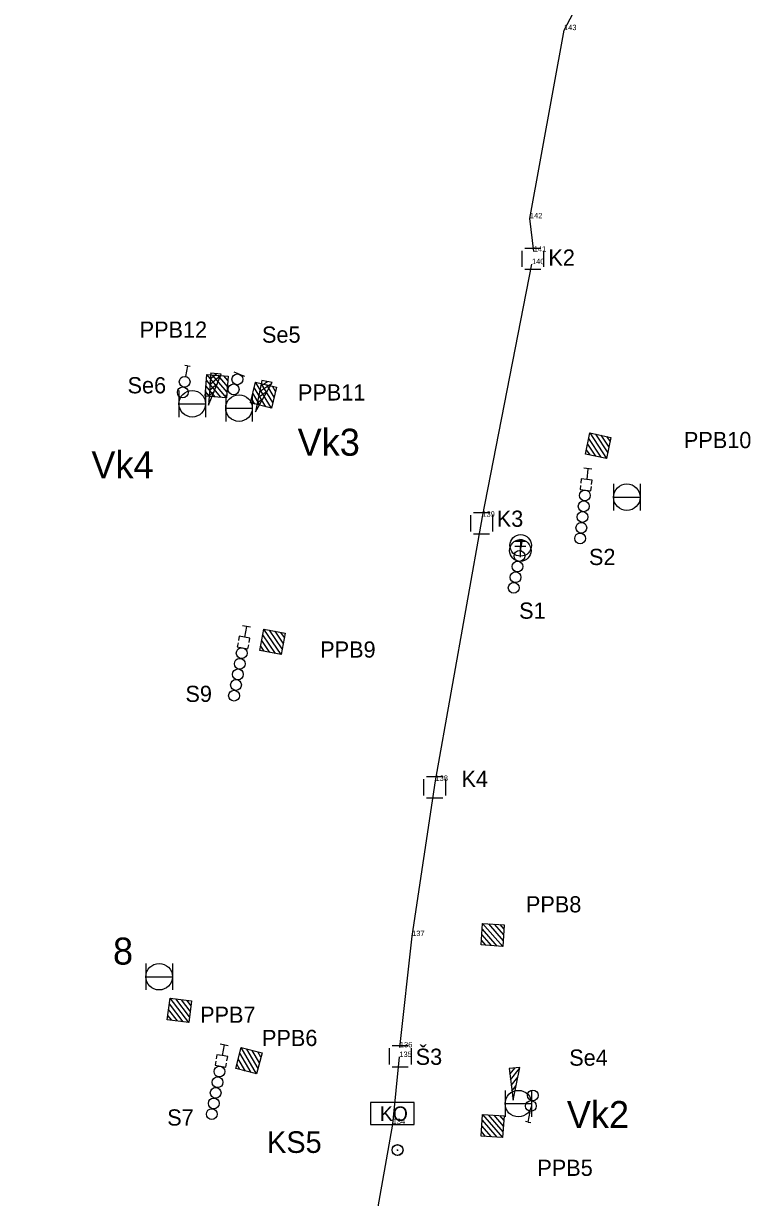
# Model space of a CAD drawing. Extents: x -866945 to -849632, y -1066564 to -1049105.
# Drawn here: x -866544.4 to -866477, y -1050152.5 to -1050043.8 of the extents above; entities that cross this region are included whole.
import ezdxf

# ---------------------------------------------------------------- set-up
doc = ezdxf.new("R2010")
doc.units = 0
for name, color, linetype in [('Vrstva 2', 7, 'Continuous'), ('Vrstva 28', 7, 'Continuous'), ('Vrstva 3', 7, 'Continuous'), ('Vrstva 31', 7, 'Continuous'), ('Vrstva 32', 7, 'Continuous'), ('Vrstva 35', 7, 'Continuous'), ('Vrstva 52', 7, 'Continuous'), ('Vrstva 6', 7, 'Continuous'), ('Vrstva 7', 7, 'Continuous')]:
    doc.layers.add(name, color=color, linetype=linetype)

msp = doc.modelspace()

# ---------------------------------------------------------------- linework, layer by layer
at = {"layer": 'Vrstva 28'}
for p, q in [((-866508.2, -1050143.71), (-866512.24, -1050143.71)), ((-866512.24, -1050143.71), (-866512.24, -1050145.73)), ((-866508.2, -1050145.73), (-866508.2, -1050143.71)), ((-866512.24, -1050145.73), (-866508.2, -1050145.73))]:
    msp.add_line(p, q, dxfattribs=at)
at = {"layer": 'Vrstva 3'}
for p, q in [((-866525.56, -1050078.48), (-866527.39, -1050076.32)), ((-866527.11, -1050077.25), (-866526.09, -1050076.38)), ((-866527.07, -1050076.73), (-866526.49, -1050076.25)), ((-866527.04, -1050076.22), (-866527.02, -1050076.21)), ((-866525.51, -1050077.95), (-866526.86, -1050076.37)), ((-866525.47, -1050077.42), (-866526.33, -1050076.41)), ((-866525.43, -1050076.89), (-866525.8, -1050076.45)), ((-866526.61, -1050078.39), (-866527.47, -1050077.38)), ((-866526.08, -1050078.43), (-866527.43, -1050076.85)), ((-866527.15, -1050077.78), (-866526.41, -1050077.15)), ((-866521.92, -1050079.31), (-866523, -1050077.53)), ((-866521.41, -1050079.44), (-866522.87, -1050077.02)), ((-866522.51, -1050077.9), (-866521.39, -1050077.16)), ((-866522.41, -1050077.39), (-866521.77, -1050076.98)), ((-866521.28, -1050078.93), (-866522.35, -1050077.15)), ((-866522.31, -1050076.88), (-866522.29, -1050076.88)), ((-866521.15, -1050078.41), (-866521.84, -1050077.28)), ((-866521.03, -1050077.9), (-866521.32, -1050077.4)), ((-866529.97, -1050077.8), (-866529.97, -1050080.26)), ((-866527.14, -1050078.35), (-866527.52, -1050077.91)), ((-866527.51, -1050077.8), (-866527.51, -1050080.26)), ((-866527.23, -1050078.82), (-866527.05, -1050078.66)), ((-866527.19, -1050078.3), (-866526.72, -1050077.9)), ((-866525.64, -1050078.2), (-866525.64, -1050080.66)), ((-866522.95, -1050079.06), (-866523.25, -1050078.56)), ((-866523.18, -1050078.2), (-866523.18, -1050080.66)), ((-866522.44, -1050079.19), (-866523.12, -1050078.05)), ((-866522.71, -1050078.93), (-866522.2, -1050078.59)), ((-866522.61, -1050078.42), (-866521.8, -1050077.88)), ((-866529.97, -1050079.03), (-866527.51, -1050079.03)), ((-866525.64, -1050079.43), (-866523.18, -1050079.43)), ((-866522.82, -1050079.45), (-866522.62, -1050079.31)), ((-866491.92, -1050081.73), (-866490.37, -1050084.1)), ((-866491.4, -1050081.84), (-866490.27, -1050083.58)), ((-866490.89, -1050081.95), (-866490.16, -1050083.06)), ((-866492.14, -1050082.77), (-866491.41, -1050083.88)), ((-866492.03, -1050082.25), (-866490.89, -1050083.99)), ((-866490.37, -1050082.06), (-866490.05, -1050082.54)), ((-866492.25, -1050083.29), (-866491.93, -1050083.77)), ((-866489.72, -1050086.45), (-866489.72, -1050088.91)), ((-866487.26, -1050086.45), (-866487.26, -1050088.91)), ((-866489.72, -1050087.68), (-866487.26, -1050087.68)), ((-866498.83, -1050091.74), (-866497.83, -1050091.74)), ((-866498.33, -1050091.74), (-866498.33, -1050092.74)), ((-866498.86, -1050092.22), (-866497.86, -1050092.22)), ((-866498.36, -1050092.22), (-866498.36, -1050093.22)), ((-866521.03, -1050102.14), (-866522.2, -1050100.42)), ((-866520.51, -1050102.23), (-866522.1, -1050099.9)), ((-866520.41, -1050101.71), (-866521.58, -1050100)), ((-866520.31, -1050101.19), (-866521.06, -1050100.09)), ((-866520.21, -1050100.67), (-866520.54, -1050100.19)), ((-866522.07, -1050101.94), (-866522.4, -1050101.46)), ((-866521.55, -1050102.04), (-866522.3, -1050100.94)), ((-866501.85, -1050127.13), (-866499.99, -1050129.26)), ((-866501.32, -1050127.16), (-866499.95, -1050128.73)), ((-866500.79, -1050127.2), (-866499.92, -1050128.2)), ((-866500.26, -1050127.23), (-866499.88, -1050127.67)), ((-866501.92, -1050128.18), (-866501.05, -1050129.18)), ((-866501.88, -1050127.65), (-866500.52, -1050129.22)), ((-866501.96, -1050128.71), (-866501.58, -1050129.15)), ((-866533.04, -1050130.83), (-866533.04, -1050133.29)), ((-866530.58, -1050130.83), (-866530.58, -1050133.29)), ((-866533.04, -1050132.06), (-866530.58, -1050132.06)), ((-866529.06, -1050136.29), (-866530.79, -1050134.06)), ((-866529, -1050135.77), (-866530.27, -1050134.12)), ((-866530.11, -1050136.16), (-866530.93, -1050135.11)), ((-866529.59, -1050136.23), (-866530.86, -1050134.58)), ((-866528.93, -1050135.24), (-866529.74, -1050134.19)), ((-866528.86, -1050134.72), (-866529.22, -1050134.26)), ((-866530.64, -1050136.09), (-866530.99, -1050135.64)), ((-866523.29, -1050140.93), (-866524.34, -1050139.14)), ((-866522.78, -1050141.06), (-866524.21, -1050138.62)), ((-866522.64, -1050140.55), (-866523.7, -1050138.76)), ((-866522.51, -1050140.03), (-866523.18, -1050138.89)), ((-866522.38, -1050139.52), (-866522.67, -1050139.02)), ((-866524.32, -1050140.66), (-866524.61, -1050140.16)), ((-866523.8, -1050140.79), (-866524.48, -1050139.65)), ((-866499.39, -1050140.58), (-866499.37, -1050140.57)), ((-866499.33, -1050141.09), (-866498.85, -1050140.51)), ((-866499.26, -1050141.61), (-866498.43, -1050140.56)), ((-866499.2, -1050142.14), (-866498.6, -1050141.37)), ((-866499.77, -1050142.58), (-866499.77, -1050145.04)), ((-866499.14, -1050142.66), (-866498.76, -1050142.17)), ((-866497.31, -1050142.58), (-866497.31, -1050145.04)), ((-866499.77, -1050143.81), (-866497.31, -1050143.81)), ((-866499.07, -1050143.18), (-866498.93, -1050142.98)), ((-866501.87, -1050144.82), (-866500.01, -1050146.95)), ((-866501.34, -1050144.85), (-866499.97, -1050146.42)), ((-866500.81, -1050144.89), (-866499.94, -1050145.89)), ((-866500.28, -1050144.92), (-866499.9, -1050145.36)), ((-866501.94, -1050145.87), (-866501.07, -1050146.87)), ((-866501.9, -1050145.34), (-866500.54, -1050146.91)), ((-866501.98, -1050146.4), (-866501.6, -1050146.84))]:
    msp.add_line(p, q, dxfattribs=at)
for points in [[(-866527.55, -1050078.32), (-866527.39, -1050076.32), (-866525.4, -1050076.48), (-866525.56, -1050078.48)], [(-866527.55, -1050078.32), (-866527.39, -1050076.32), (-866525.4, -1050076.48), (-866525.56, -1050078.48)], [(-866523.35, -1050078.96), (-866522.87, -1050077.02), (-866520.93, -1050077.5), (-866521.41, -1050079.44)], [(-866523.35, -1050078.96), (-866522.87, -1050077.02), (-866520.93, -1050077.5), (-866521.41, -1050079.44)], [(-866489.97, -1050082.14), (-866490.37, -1050084.1), (-866492.33, -1050083.69), (-866491.92, -1050081.73)], [(-866489.97, -1050082.14), (-866490.37, -1050084.1), (-866492.33, -1050083.69), (-866491.92, -1050081.73)], [(-866522.48, -1050101.86), (-866522.1, -1050099.9), (-866520.14, -1050100.27), (-866520.51, -1050102.23)], [(-866522.48, -1050101.86), (-866522.1, -1050099.9), (-866520.14, -1050100.27), (-866520.51, -1050102.23)], [(-866499.85, -1050127.26), (-866499.99, -1050129.26), (-866501.98, -1050129.12), (-866501.85, -1050127.13)], [(-866499.85, -1050127.26), (-866499.99, -1050129.26), (-866501.98, -1050129.12), (-866501.85, -1050127.13)], [(-866531.05, -1050136.04), (-866530.79, -1050134.06), (-866528.81, -1050134.31), (-866529.06, -1050136.29)], [(-866531.05, -1050136.04), (-866530.79, -1050134.06), (-866528.81, -1050134.31), (-866529.06, -1050136.29)], [(-866524.71, -1050140.56), (-866524.21, -1050138.62), (-866522.27, -1050139.12), (-866522.78, -1050141.06)], [(-866524.71, -1050140.56), (-866524.21, -1050138.62), (-866522.27, -1050139.12), (-866522.78, -1050141.06)], [(-866499.87, -1050144.95), (-866500.01, -1050146.95), (-866502, -1050146.81), (-866501.87, -1050144.82)], [(-866499.87, -1050144.95), (-866500.01, -1050146.95), (-866502, -1050146.81), (-866501.87, -1050144.82)]]:
    msp.add_lwpolyline(points, close=True, dxfattribs=at)
for points in [[(-866527.55, -1050078.32), (-866527.39, -1050076.32), (-866525.4, -1050076.48), (-866525.56, -1050078.48), (-866527.55, -1050078.32)], [(-866527.55, -1050078.32), (-866527.39, -1050076.32), (-866525.4, -1050076.48), (-866525.56, -1050078.48), (-866527.55, -1050078.32)], [(-866527.25, -1050079.15), (-866526.05, -1050076.28), (-866527.03, -1050076.21), (-866527.25, -1050079.15)], [(-866527.25, -1050079.15), (-866526.05, -1050076.28), (-866527.03, -1050076.21), (-866527.25, -1050079.15)], [(-866523.35, -1050078.96), (-866522.87, -1050077.02), (-866520.93, -1050077.5), (-866521.41, -1050079.44), (-866523.35, -1050078.96)], [(-866523.35, -1050078.96), (-866522.87, -1050077.02), (-866520.93, -1050077.5), (-866521.41, -1050079.44), (-866523.35, -1050078.96)], [(-866522.88, -1050079.77), (-866521.34, -1050077.07), (-866522.31, -1050076.87), (-866522.88, -1050079.77)], [(-866522.88, -1050079.77), (-866521.34, -1050077.07), (-866522.31, -1050076.87), (-866522.88, -1050079.77)], [(-866489.97, -1050082.14), (-866490.37, -1050084.1), (-866492.33, -1050083.69), (-866491.92, -1050081.73), (-866489.97, -1050082.14)], [(-866489.97, -1050082.14), (-866490.37, -1050084.1), (-866492.33, -1050083.69), (-866491.92, -1050081.73), (-866489.97, -1050082.14)], [(-866522.48, -1050101.86), (-866522.1, -1050099.9), (-866520.14, -1050100.27), (-866520.51, -1050102.23), (-866522.48, -1050101.86)], [(-866522.48, -1050101.86), (-866522.1, -1050099.9), (-866520.14, -1050100.27), (-866520.51, -1050102.23), (-866522.48, -1050101.86)], [(-866499.85, -1050127.26), (-866499.99, -1050129.26), (-866501.98, -1050129.12), (-866501.85, -1050127.13), (-866499.85, -1050127.26)], [(-866499.85, -1050127.26), (-866499.99, -1050129.26), (-866501.98, -1050129.12), (-866501.85, -1050127.13), (-866499.85, -1050127.26)], [(-866531.05, -1050136.04), (-866530.79, -1050134.06), (-866528.81, -1050134.31), (-866529.06, -1050136.29), (-866531.05, -1050136.04)], [(-866531.05, -1050136.04), (-866530.79, -1050134.06), (-866528.81, -1050134.31), (-866529.06, -1050136.29), (-866531.05, -1050136.04)], [(-866524.71, -1050140.56), (-866524.21, -1050138.62), (-866522.27, -1050139.12), (-866522.78, -1050141.06), (-866524.71, -1050140.56)], [(-866524.71, -1050140.56), (-866524.21, -1050138.62), (-866522.27, -1050139.12), (-866522.78, -1050141.06), (-866524.71, -1050140.56)], [(-866499.03, -1050143.5), (-866498.41, -1050140.45), (-866499.39, -1050140.57), (-866499.03, -1050143.5)], [(-866499.03, -1050143.5), (-866498.41, -1050140.45), (-866499.39, -1050140.57), (-866499.03, -1050143.5)], [(-866499.87, -1050144.95), (-866500.01, -1050146.95), (-866502, -1050146.81), (-866501.87, -1050144.82), (-866499.87, -1050144.95)], [(-866499.87, -1050144.95), (-866500.01, -1050146.95), (-866502, -1050146.81), (-866501.87, -1050144.82), (-866499.87, -1050144.95)]]:
    msp.add_lwpolyline(points, dxfattribs=at)
for centre, radius in [((-866528.74, -1050079.03), 1.23), ((-866524.41, -1050079.43), 1.23), ((-866488.49, -1050087.68), 1.23), ((-866498.36, -1050092.62), 1), ((-866498.33, -1050092.14), 1), ((-866531.81, -1050132.06), 1.23), ((-866498.54, -1050143.81), 1.23)]:
    msp.add_circle(centre, radius, dxfattribs=at)
at = {"layer": 'Vrstva 32'}
msp.add_lwpolyline([(-866544.37, -1050204.45), (-866541, -1050204.46), (-866531.57, -1050205.56), (-866526.12, -1050206.75), (-866521.22, -1050207.39), (-866517.57, -1050187.41), (-866510.18, -1050145.7), (-866509.56, -1050139.49)], dxfattribs=at)
at = {"layer": 'Vrstva 35'}
for p, q in [((-866494.31, -1050044.45), (-866492.94, -1050041.88)), ((-866497.47, -1050061.87), (-866494.31, -1050044.45)), ((-866497.11, -1050064.95), (-866497.47, -1050061.87)), ((-866498.2, -1050066.37), (-866498.2, -1050064.87)), ((-866497.95, -1050064.62), (-866496.45, -1050064.62)), ((-866496.2, -1050064.87), (-866496.2, -1050066.37)), ((-866501.87, -1050089.49), (-866497.28, -1050066.11)), ((-866496.45, -1050066.62), (-866497.95, -1050066.62)), ((-866506.21, -1050113.94), (-866501.87, -1050089.49)), ((-866502.95, -1050090.84), (-866502.95, -1050089.34)), ((-866502.7, -1050089.09), (-866501.2, -1050089.09)), ((-866500.95, -1050089.34), (-866500.95, -1050090.84)), ((-866501.2, -1050091.09), (-866502.7, -1050091.09)), ((-866508.38, -1050128.3), (-866506.21, -1050113.94)), ((-866507.3, -1050115.28), (-866507.3, -1050113.78)), ((-866507.05, -1050113.53), (-866505.55, -1050113.53)), ((-866505.3, -1050113.78), (-866505.3, -1050115.28)), ((-866505.55, -1050115.53), (-866507.05, -1050115.53)), ((-866509.51, -1050138.6), (-866508.38, -1050128.3)), ((-866510.23, -1050138.43), (-866508.73, -1050138.43)), ((-866510.48, -1050140.18), (-866510.48, -1050138.68)), ((-866508.48, -1050138.68), (-866508.48, -1050140.18)), ((-866508.73, -1050140.43), (-866510.23, -1050140.43))]:
    msp.add_line(p, q, dxfattribs=at)
at = {"layer": 'Vrstva 6'}
for p, q in [((-866529.18, -1050075.52), (-866529.43, -1050075.48)), ((-866529.18, -1050075.52), (-866529.36, -1050076.5)), ((-866529.18, -1050075.52), (-866528.93, -1050075.56)), ((-866524.38, -1050076.3), (-866524.85, -1050076.12)), ((-866524.38, -1050076.3), (-866523.91, -1050076.48)), ((-866491.73, -1050085.08), (-866492.47, -1050085)), ((-866492.1, -1050085.04), (-866492.1, -1050085.04)), ((-866498.18, -1050091.64), (-866498.43, -1050091.6)), ((-866498.18, -1050091.64), (-866498.36, -1050092.62)), ((-866498.18, -1050091.64), (-866497.93, -1050091.68)), ((-866523.35, -1050099.72), (-866524.09, -1050099.58)), ((-866523.72, -1050099.65), (-866523.72, -1050099.65)), ((-866525.41, -1050138.45), (-866526.15, -1050138.31)), ((-866525.78, -1050138.38), (-866525.78, -1050138.38)), ((-866497.64, -1050145.51), (-866497.46, -1050144.53)), ((-866497.64, -1050145.51), (-866497.89, -1050145.47)), ((-866497.64, -1050145.51), (-866497.39, -1050145.55))]:
    msp.add_line(p, q, dxfattribs=at)
for points in [[(-866492.1, -1050085.04), (-866492.21, -1050086.03), (-866492.71, -1050085.98), (-866492.75, -1050086.38)], [(-866491.76, -1050086.49), (-866491.71, -1050086.09), (-866492.21, -1050086.03)], [(-866492.78, -1050086.59), (-866492.82, -1050086.97), (-866491.82, -1050087.08), (-866491.78, -1050086.7)], [(-866523.72, -1050099.65), (-866523.9, -1050100.63), (-866524.39, -1050100.55), (-866524.46, -1050100.94)], [(-866524.5, -1050101.16), (-866524.57, -1050101.53), (-866523.58, -1050101.71), (-866523.51, -1050101.33)], [(-866523.47, -1050101.12), (-866523.4, -1050100.72), (-866523.9, -1050100.63)], [(-866525.78, -1050138.38), (-866525.96, -1050139.36), (-866526.45, -1050139.28), (-866526.52, -1050139.67)], [(-866525.53, -1050139.85), (-866525.46, -1050139.45), (-866525.96, -1050139.36)], [(-866526.56, -1050139.89), (-866526.63, -1050140.26), (-866525.64, -1050140.44), (-866525.57, -1050140.06)]]:
    msp.add_lwpolyline(points, dxfattribs=at)
for centre in [(-866529.44, -1050077), (-866524.56, -1050076.77), (-866529.62, -1050077.98), (-866524.91, -1050077.7), (-866492.38, -1050087.52), (-866492.49, -1050088.52), (-866492.6, -1050089.51), (-866492.71, -1050090.51), (-866492.82, -1050091.5), (-866498.44, -1050093.12), (-866498.62, -1050094.1), (-866498.8, -1050095.09), (-866498.97, -1050096.07), (-866524.34, -1050103.1), (-866524.16, -1050102.11), (-866524.51, -1050104.08), (-866524.69, -1050105.06), (-866524.87, -1050106.05), (-866526.22, -1050140.84), (-866526.4, -1050141.83), (-866526.57, -1050142.81), (-866497.2, -1050143.05), (-866526.75, -1050143.79), (-866497.38, -1050144.03), (-866526.93, -1050144.78)]:
    msp.add_circle(centre, 0.5, dxfattribs=at)
at = {"layer": 'Vrstva 7'}
for p, q in [((-866509.79, -1050148.1), (-866509.69, -1050148.1)), ((-866509.77, -1050148.11), (-866509.67, -1050148.11))]:
    msp.add_line(p, q, dxfattribs=at)
for centre in [(-866509.74, -1050148.1), (-866509.72, -1050148.11)]:
    msp.add_circle(centre, 0.5, dxfattribs=at)

# ---------------------------------------------------------------- texts
at = {"layer": 'Vrstva 2'}
for s, p in [('Vk3', (-866518.98, -1050083.84)), ('Vk4', (-866538.08, -1050085.92)), ('8', (-866536.08, -1050130.94)), ('Vk2', (-866494.05, -1050146.07))]:
    msp.add_text(s, height=2.5, dxfattribs=at).set_placement(p)
at = {"layer": 'Vrstva 28'}
for s, height, p in [('KO', 1.344, (-866511.37, -1050145.41)), ('KS5', 2, (-866521.81, -1050148.37))]:
    msp.add_text(s, height=height, dxfattribs=at).set_placement(p)
at = {"layer": 'Vrstva 3'}
for s, p in [('PPB12', (-866533.61, -1050072.92)), ('PPB11', (-866518.95, -1050078.73)), ('PPB10', (-866483.21, -1050083.14)), ('PPB9', (-866516.89, -1050102.53)), ('PPB8', (-866497.84, -1050126.11)), ('PPB7', (-866528.01, -1050136.33)), ('PPB6', (-866522.28, -1050138.48)), ('PPB5', (-866496.78, -1050150.5))]:
    msp.add_text(s, height=1.5, dxfattribs=at).set_placement(p)
at = {"layer": 'Vrstva 31'}
for s, p in [('K2', (-866495.76, -1050066.25)), ('K3', (-866500.54, -1050090.42)), ('K4', (-866503.81, -1050114.5)), ('Š3', (-866508.05, -1050140.22))]:
    msp.add_text(s, height=1.5, dxfattribs=at).set_placement(p)
at = {"layer": 'Vrstva 52'}
for s, p in [('143', (-866494.31, -1050044.45)), ('142', (-866497.47, -1050061.87)), ('141', (-866497.11, -1050064.95)), ('140', (-866497.28, -1050066.11)), ('139', (-866501.87, -1050089.49)), ('138', (-866506.21, -1050113.94)), ('137', (-866508.38, -1050128.3)), ('136', (-866509.51, -1050138.6)), ('135', (-866509.56, -1050139.49)), ('134', (-866510.18, -1050145.7))]:
    msp.add_text(s, height=0.5, dxfattribs=at).set_placement(p)
at = {"layer": 'Vrstva 6'}
for s, p in [('Se5', (-866522.28, -1050073.38)), ('Se6', (-866534.73, -1050078.07)), ('S2', (-866492, -1050093.96)), ('S1', (-866498.47, -1050098.93)), ('S9', (-866529.37, -1050106.63)), ('Se4', (-866493.83, -1050140.3)), ('S7', (-866531.06, -1050145.84))]:
    msp.add_text(s, height=1.5, dxfattribs=at).set_placement(p)

doc.saveas('drawing.dxf')
